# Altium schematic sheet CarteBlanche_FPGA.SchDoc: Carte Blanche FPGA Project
size A1; DrawnBy: SRKH; Engineer: SRKH; DocumentNumber: 1; Revision: CB500E; SheetNumber: 1; SheetTotal: 1
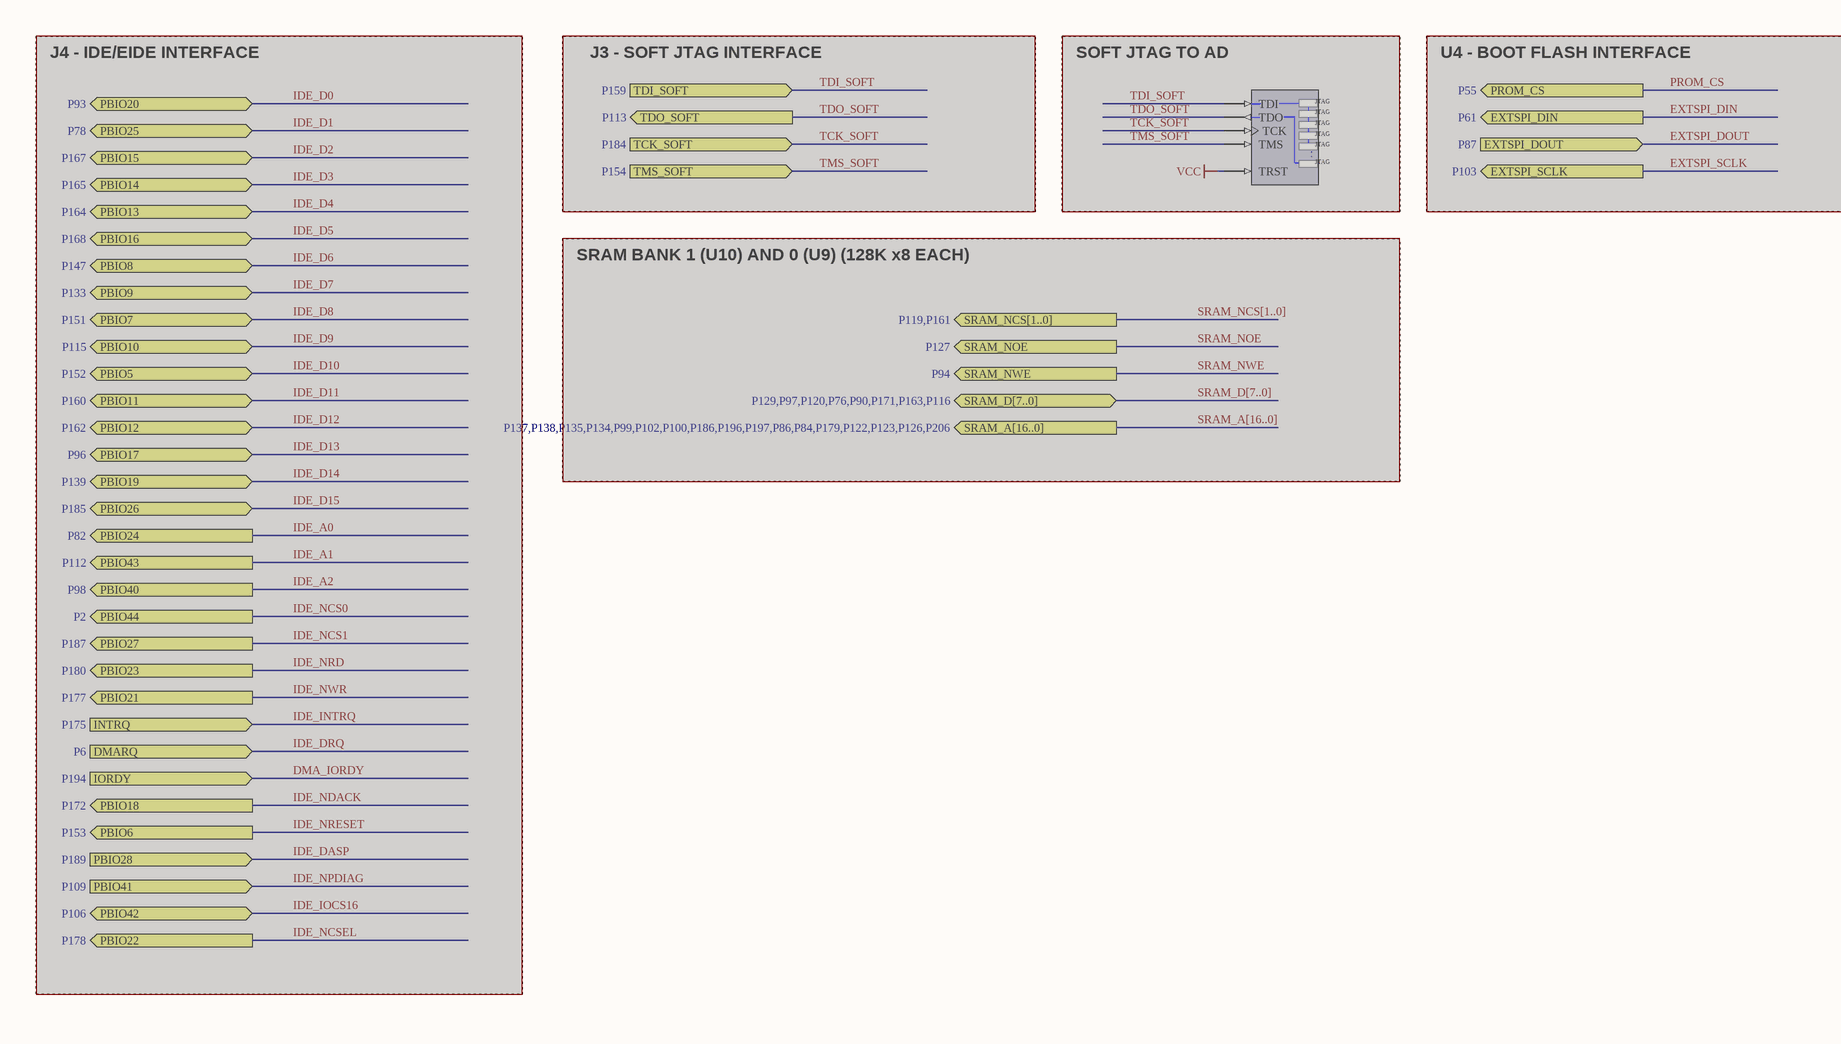
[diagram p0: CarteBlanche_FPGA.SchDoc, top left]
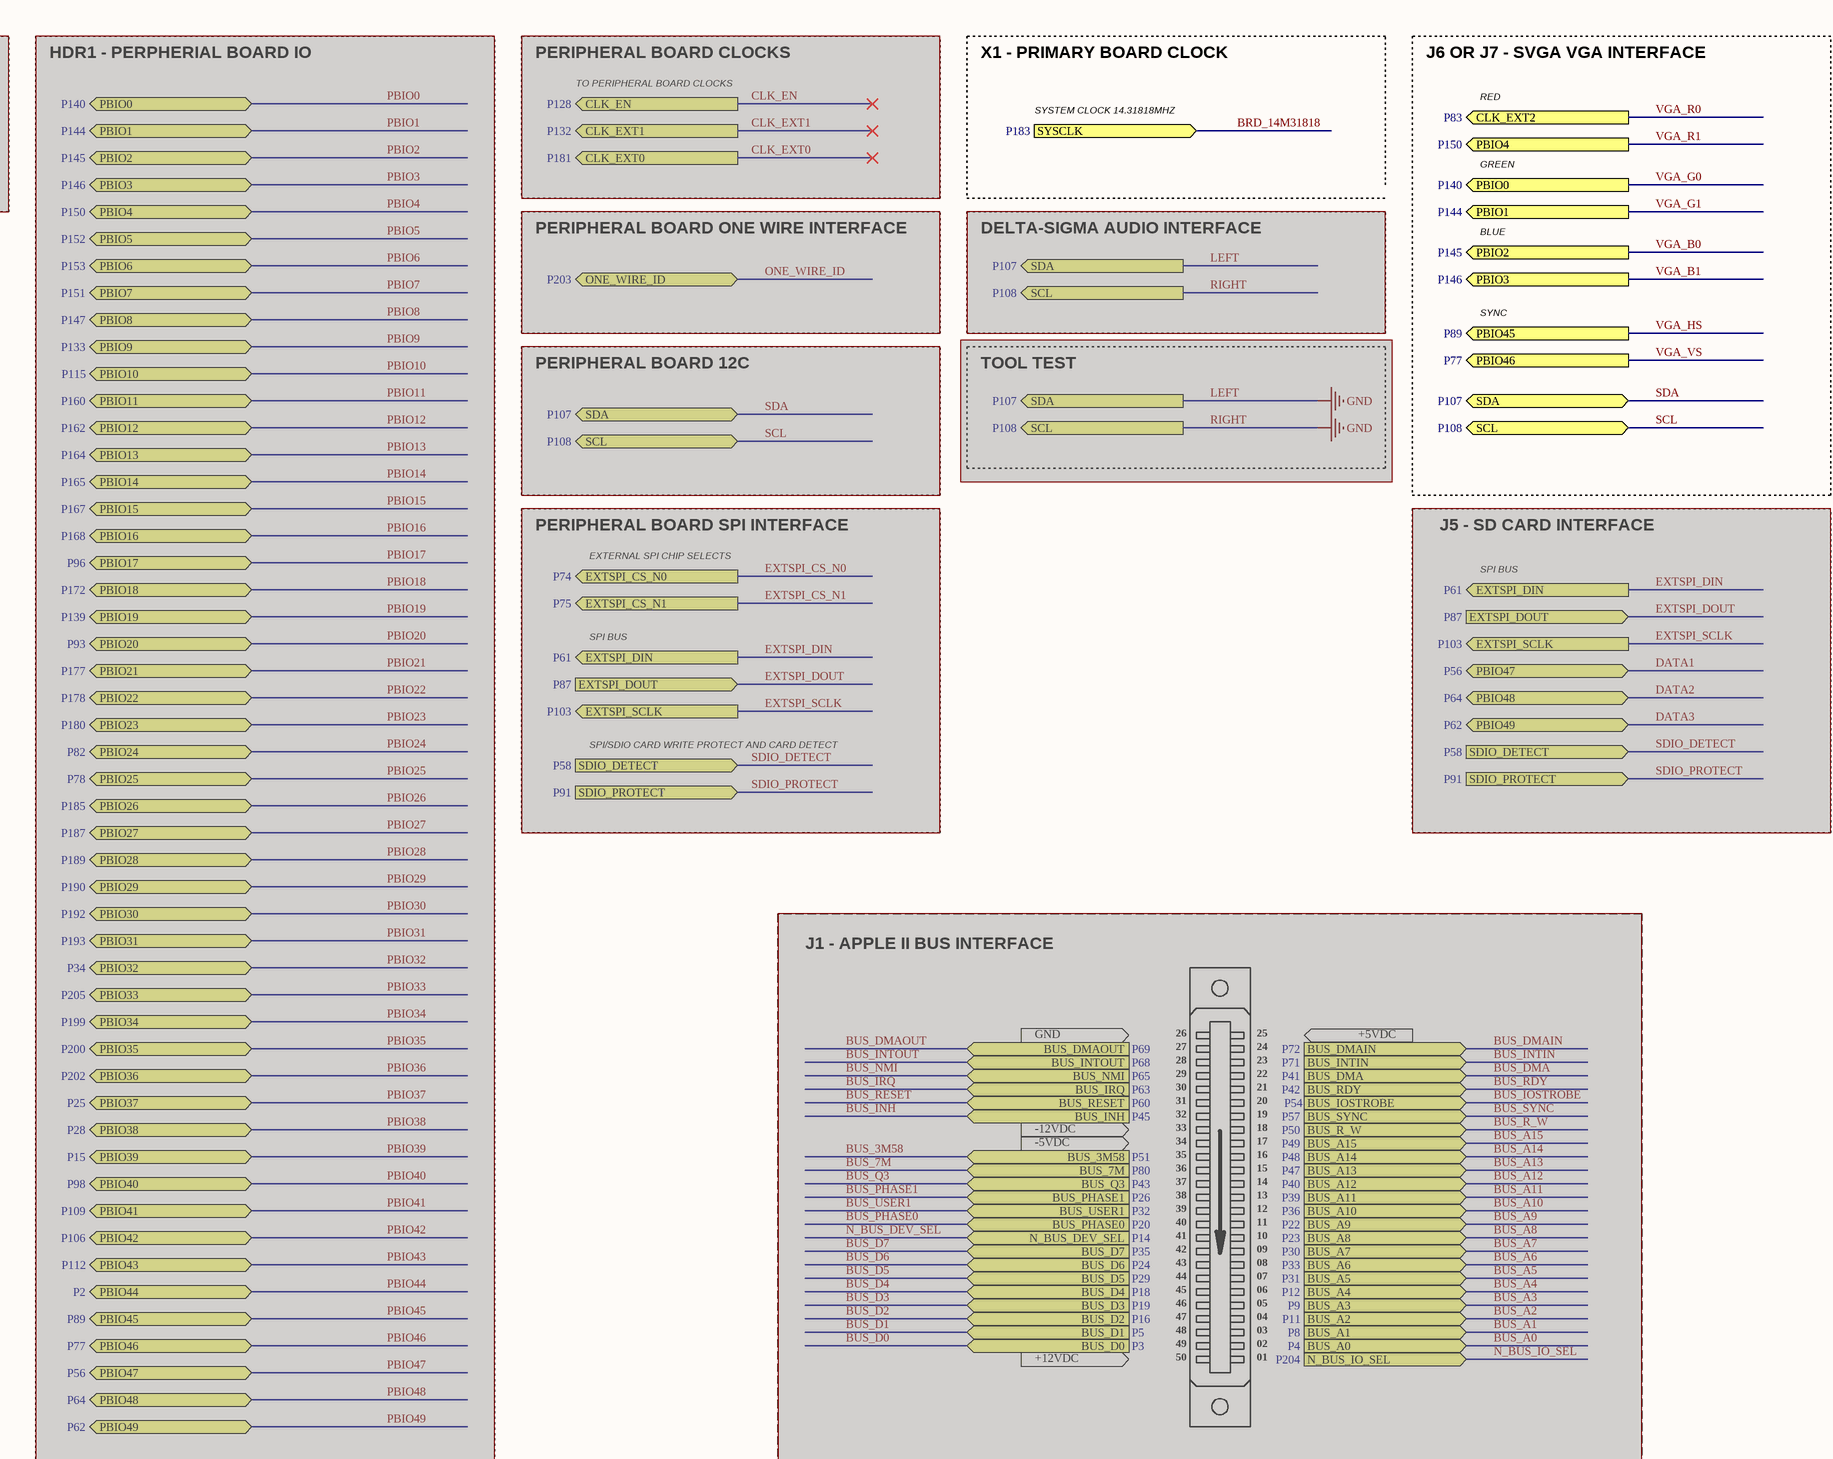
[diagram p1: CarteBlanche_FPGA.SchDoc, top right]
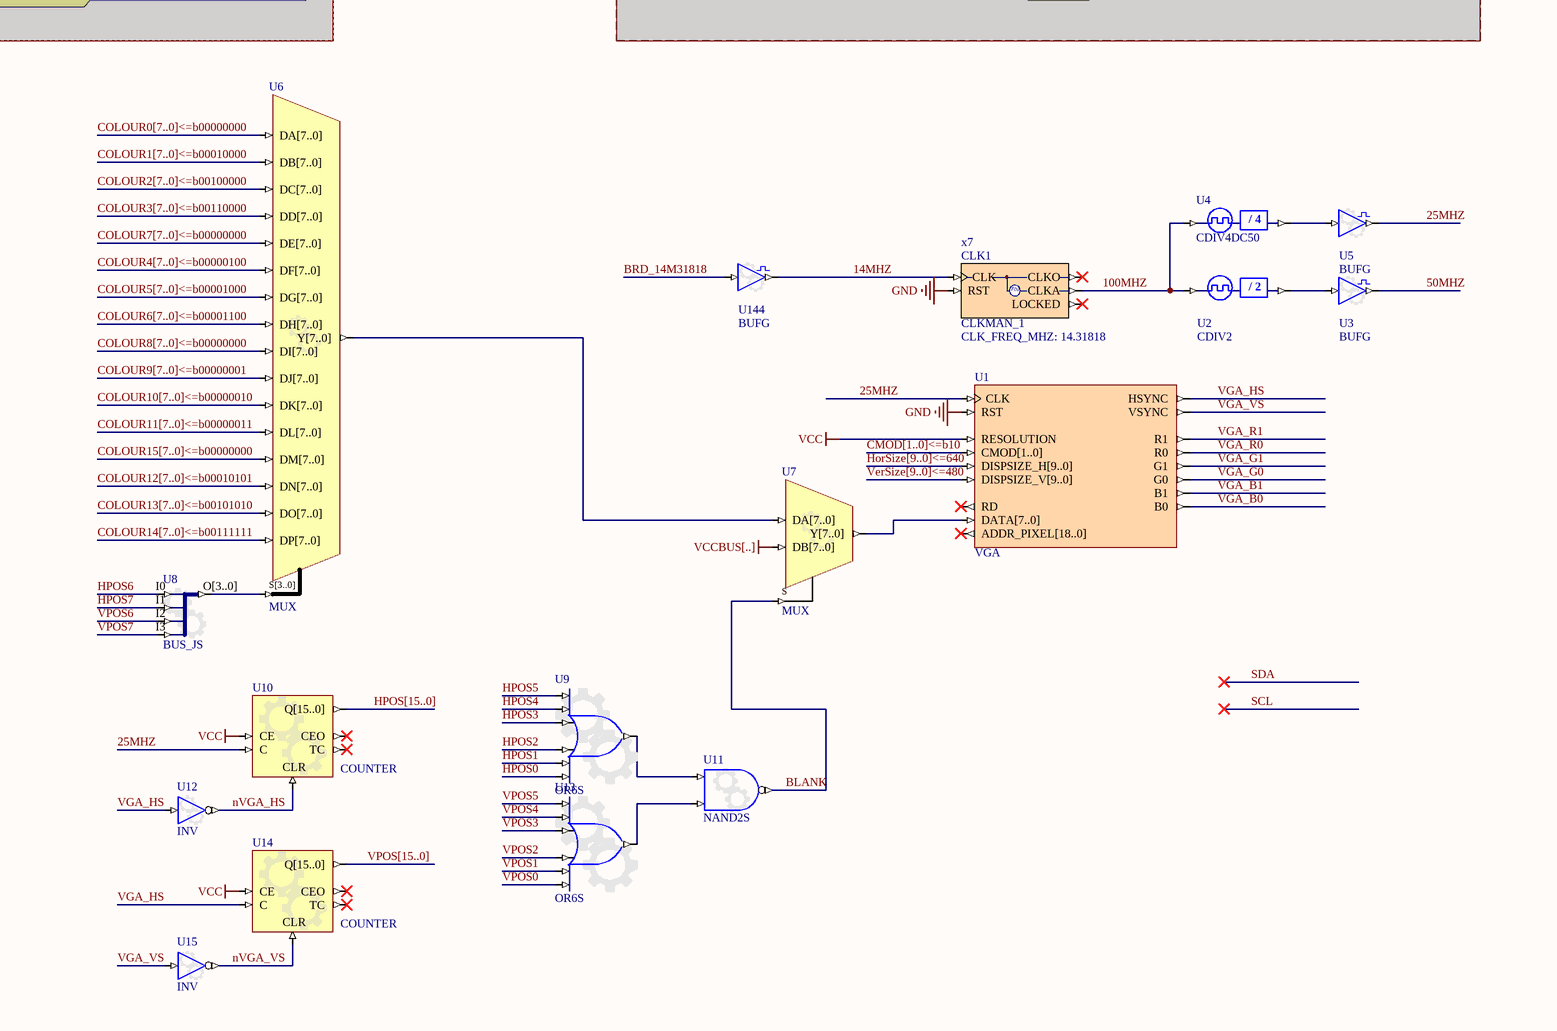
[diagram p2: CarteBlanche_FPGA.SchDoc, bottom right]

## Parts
CLK1  CLKMAN_1  CLK_FREQ_MHZ: 14.31818  ClkA_Operation: x7
NEXUS_JTAG_PORT  NEXUS_JTAG_PORT  (value not drawn)  (masked out: inside a compile mask, not in the netlist)
U1  VGA
U2  CDIV2
U3  BUFG
U4  CDIV4DC50
U5  BUFG
U6  MUX
U7  MUX
U8  BUS_JS
U9  OR6S
U10  COUNTER
U11  NAND2S
U12  INV
U13  OR6S
U14  COUNTER
U15  INV
U144  BUFG

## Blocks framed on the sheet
SOFT JTAG TO AD: NEXUS_JTAG_PORT

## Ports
BUS_3M58 (in, see P51), BUS_7M (in, see P80), BUS_A0 (in, see P4), BUS_A1 (in, see P8), BUS_A2 (in, see P11), BUS_A3 (in, see P9), BUS_A4 (in, see P12), BUS_A5 (in, see P31), BUS_A6 (in, see P33), BUS_A7 (in, see P30), BUS_A8 (in, see P23), BUS_A9 (in, see P22), BUS_A10 (in, see P36), BUS_A11 (in, see P39), BUS_A12 (in, see P40), BUS_A13 (in, see P47), BUS_A14 (in, see P48), BUS_A15 (in, see P49), BUS_D0 (in, see P3), BUS_D1 (in, see P5), BUS_D2 (in, see P16), BUS_D3 (in, see P19), BUS_D4 (in, see P18), BUS_D5 (in, see P29), BUS_D6 (in, see P24), BUS_D7 (in, see P35), BUS_DMA (in, see P41), BUS_DMAIN (in, see P72), BUS_DMAOUT (in, see P69), BUS_INH (in, see P45), BUS_INTIN (in, see P71), BUS_INTOUT (in, see P68), BUS_IOSTROBE (in, see P54), BUS_IRQ (in, see P63), BUS_NMI (in, see P65), BUS_PHASE0 (in, see P20), BUS_PHASE1 (in, see P26), BUS_Q3 (in, see P43), BUS_R_W (in, see P50), BUS_RDY (in, see P42), BUS_RESET (in, see P60), BUS_SYNC (in, see P57), BUS_USER1 (in, see P32), CLK_EN (out, see P128), CLK_EXT0 (out, see P181), CLK_EXT1 (out, see P132), CLK_EXT2 (out, see P83), DMARQ (in, see P6), EXTSPI_CS_N0 (out, see P74), EXTSPI_CS_N1 (out, see P75), EXTSPI_DIN (out, see P61), EXTSPI_DOUT (in, see P87), EXTSPI_SCLK (out, see P103), INTRQ (in, see P175), IORDY (in, see P194), N_BUS_DEV_SEL (in, see P14), N_BUS_IO_SEL (in, see P204), ONE_WIRE_ID (bidir, see P203), PBIO0 (bidir, see P140), PBIO0 (out, see P140), PBIO1 (bidir, see P144), PBIO1 (out, see P144), PBIO2 (bidir, see P145), PBIO2 (out, see P145), PBIO3 (bidir, see P146), PBIO3 (out, see P146), PBIO4 (bidir, see P150), PBIO4 (out, see P150), PBIO5 (bidir, see P152), PBIO6 (bidir, see P153), PBIO6 (out, see P153), PBIO7 (bidir, see P151), PBIO8 (bidir, see P147), PBIO9 (bidir, see P133), PBIO10 (bidir, see P115), PBIO11 (bidir, see P160), PBIO12 (bidir, see P162), PBIO13 (bidir, see P164), PBIO14 (bidir, see P165), PBIO15 (bidir, see P167), PBIO16 (bidir, see P168), PBIO17 (bidir, see P96), PBIO18 (bidir, see P172), PBIO18 (out, see P172), PBIO19 (bidir, see P139), PBIO20 (bidir, see P93), PBIO21 (bidir, see P177), PBIO21 (out, see P177), PBIO22 (bidir, see P178), PBIO22 (out, see P178), PBIO23 (bidir, see P180), PBIO23 (out, see P180), PBIO24 (bidir, see P82), PBIO24 (out, see P82), PBIO25 (bidir, see P78), PBIO26 (bidir, see P185), PBIO27 (bidir, see P187), PBIO27 (out, see P187), PBIO28 (bidir, see P189), PBIO28 (in, see P189), PBIO29 (bidir, see P190), PBIO30 (bidir, see P192), PBIO31 (bidir, see P193), PBIO32 (bidir, see P34), PBIO33 (bidir, see P205), PBIO34 (bidir, see P199), PBIO35 (bidir, see P200), PBIO36 (bidir, see P202), PBIO37 (bidir, see P25), PBIO38 (bidir, see P28), PBIO39 (bidir, see P15), PBIO40 (bidir, see P98), PBIO40 (out, see P98), PBIO41 (bidir, see P109), PBIO41 (in, see P109), PBIO42 (bidir, see P106), PBIO43 (bidir, see P112), PBIO43 (out, see P112), PBIO44 (bidir, see P2), PBIO44 (out, see P2), PBIO45 (bidir, see P89), PBIO45 (out, see P89), PBIO46 (bidir, see P77), PBIO46 (out, see P77), PBIO47 (bidir, see P56), PBIO48 (bidir, see P64), PBIO49 (bidir, see P62), PROM_CS (out, see P55), SCL (bidir, see P108), SCL (out, see P108), SDA (bidir, see P107), SDA (out, see P107), SDIO_DETECT (in, see P58), SDIO_PROTECT (in, see P91), SRAM_A[16..0] (out, see P137,P138,P135,P134,P99,P102,P100,P186,P196,P197,P86,P84,P179,P122,P123,P126,P206), SRAM_D[7..0] (bidir, see P129,P97,P120,P76,P90,P171,P163,P116), SRAM_NCS[1..0] (out, see P119,P161), SRAM_NOE (out, see P127), SRAM_NWE (out, see P94), SYSCLK (in, see P183), TCK_SOFT (in, see P184), TDI_SOFT (in, see P159), TDO_SOFT (out, see P113), TMS_SOFT (in, see P154)

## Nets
GND: CLK1.RST U1.RST
VCC: U1.RESOLUTION U10.CE U14.CE
VCCBUS[..]: U7.DB[7..0]
14MHZ: CLK1.CLK U144.O
25MHZ: U1.CLK U5.O U10.C
50MHZ: U3.O
100MHZ: CLK1.CLKA U2.CLKIN U4.CLKIN
BLANK: U7.S U11.O
BRD_14M31818: U144.I ; port SYSCLK
HPOS0: U9.I5
HPOS1: U9.I4
HPOS2: U9.I3
HPOS3: U9.I2
HPOS4: U9.I1
HPOS5: U9.I0
HPOS6: U8.I0
HPOS7: U8.I1
nVGA_HS: U10.CLR U12.O
nVGA_VS: U14.CLR U15.O
VGA_B0: U1.B0 ; port PBIO2
VGA_B1: U1.B1 ; port PBIO3
VGA_G0: U1.G0 ; port PBIO0
VGA_G1: U1.G1 ; port PBIO1
VGA_HS: U1.HSYNC U12.I U14.C ; port PBIO45
VGA_R0: U1.R0 ; port CLK_EXT2
VGA_R1: U1.R1 ; port PBIO4
VGA_VS: U1.VSYNC U15.I ; port PBIO46
VPOS0: U13.I5
VPOS1: U13.I4
VPOS2: U13.I3
VPOS3: U13.I2
VPOS4: U13.I1
VPOS5: U13.I0
VPOS6: U8.I2
VPOS7: U8.I3
NetU2_CLKDV: U2.CLKDV U3.I
NetU4_CLKDV: U4.CLKDV U5.I
NetU9_O: U9.O U11.I0
NetU11_I1: U11.I1 U13.O

Not connected (* = marked no-connect by the designer): CLK1 CLKO* LOCKED*; U1 ADDR_PIXEL[18..0]* CMOD[1..0] DATA[7..0] DISPSIZE_H[9..0] DISPSIZE_V[9..0] RD*; U6 DA[7..0] DB[7..0] DC[7..0] DD[7..0] DE[7..0] DF[7..0] DG[7..0] DH[7..0] DI[7..0] DJ[7..0] DK[7..0] DL[7..0] DM[7..0] DN[7..0] DO[7..0] DP[7..0] S[3..0] Y[7..0]; U7 DA[7..0] Y[7..0]; U8 O[3..0]; U10 CEO* Q[15..0] TC*; U14 CEO* Q[15..0] TC*

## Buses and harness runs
bus CMOD[1..0]<=b10
bus COLOUR0[7..0]<=b00000000
bus COLOUR1[7..0]<=b00010000
bus COLOUR2[7..0]<=b00100000
bus COLOUR3[7..0]<=b00110000
bus COLOUR4[7..0]<=b00000100
bus COLOUR5[7..0]<=b00001000
bus COLOUR6[7..0]<=b00001100
bus COLOUR7[7..0]<=b00000000
bus COLOUR8[7..0]<=b00000000
bus COLOUR9[7..0]<=b00000001
bus COLOUR10[7..0]<=b00000010
bus COLOUR11[7..0]<=b00000011
bus COLOUR12[7..0]<=b00010101
bus COLOUR13[7..0]<=b00101010
bus COLOUR14[7..0]<=b00111111
bus COLOUR15[7..0]<=b00000000
bus HorSize[9..0]<=640
bus HPOS[15..0]
bus VerSize[9..0]<=480
bus VPOS[15..0]

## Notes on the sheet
- J4 - IDE/EIDE INTERFACE
- J3 - SOFT JTAG INTERFACE
- U4 - BOOT FLASH INTERFACE
- HDR1 - PERPHERIAL BOARD IO
- PERIPHERAL BOARD CLOCKS
- X1 - PRIMARY BOARD CLOCK
- J6 OR J7 - SVGA VGA INTERFACE
- TO PERIPHERAL BOARD CLOCKS
- SYSTEM CLOCK 14.31818MHZ
- RED
- GREEN
- SRAM BANK 1 (U10) AND 0 (U9) (128K x8 EACH)
- PERIPHERAL BOARD ONE WIRE INTERFACE
- DELTA-SIGMA AUDIO INTERFACE
- BLUE
- SYNC
- PERIPHERAL BOARD 12C
- TOOL TEST
- PERIPHERAL BOARD SPI INTERFACE
- J5 - SD CARD INTERFACE
- EXTERNAL SPI CHIP SELECTS
- SPI BUS
- SPI/SDIO CARD WRITE PROTECT AND CARD DETECT
- J1 - APPLE II BUS INTERFACE
- GND
- 26
- 27
- 28
- 29
- 25
- 24
- 23
- 22
- +5VDC
- -12VDC
- 30
- 31
- 32
- 33
- 34
- 21
- 20
- 19
- 18
- 17
- -5VDC
- 35
- 36
- 37
- 38
- 39
- 16
- 15
- 14
- 13
- 12
- 40
- 41
- 42
- 43
- 44
- 11
- 10
- 09
- 08
- 07
- 45
- 46
- 47
- 48
- 49
- 06
- 05
- 04
- 03
- 02
- +12VDC
- 50
- 01

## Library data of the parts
CLK1 = CLKMAN_1: Single Operational Output Clock Manager; Clk_Count: 1
NEXUS_JTAG_PORT = NEXUS_JTAG_PORT: Soft Nexus-Chain Connector; NEXUS_JTAG_CONNECTOR: True
U1 = VGA: VGA Controller
U2 = CDIV2: Clock Divider by 2; DivisorRate: 2; ArchiveName: GENERIC; VHDLIB_SIM: GENERIC_LIB
U3 U5 U144 = BUFG: Configurable Global Clock Buffer; ConfiguratorName: GENERIC_BUFFER; ConfigurationParameters: {}Version[1.1]{}SignalCount[1]{}SignalWidth0[1]{}OutputOption0[Global Clock]{}EnableMode[None]{}ShowPinNames[False]{}
U4 = CDIV4DC50: Clock Divider by 4 with 50% Duty Cycle Output; DivisorRate: 4; ArchiveName: GENERIC; VHDLIB_SIM: GENERIC_LIB; XilinxEquivalent: CLK_DIV4; DutyCycle: 50
U6 = MUX: Configurable Mutliplexer; ConfigurationParameters: {}Version[1.0]{}ShowEnable[False]{}BusInputs[True]{}BusOutputs[True]{}SignalWidth[8]{}Type[Multiplexer]{}RegisterOutputs[False]{}NegativeClockEdge[False]{}ShowPinNames[True]{}InvertSingleSignal[False]{}SignalCount[16]{}Invert0[False]{}Invert1[False]{}Invert2[False]{}Invert3[False]{}Invert4[False]{}Invert5[False]{}Invert6[False]{}Invert7[False]{}Invert8[False]{}Invert9[False]{}Invert10[False]{}Invert11[False]{}Invert12[False]{}Invert13[False]{}Invert14[False]{}Invert15[False]{}; ConfiguratorName: GENERIC_MULTIPLEXER
U7 = MUX: Configurable Mutliplexer; ConfigurationParameters: {}Version[1.0]{}ShowEnable[False]{}BusInputs[True]{}BusOutputs[True]{}SignalWidth[8]{}Type[Multiplexer]{}RegisterOutputs[False]{}NegativeClockEdge[False]{}ShowPinNames[True]{}InvertSingleSignal[False]{}SignalCount[2]{}Invert0[False]{}Invert1[False]{}; ConfiguratorName: GENERIC_MULTIPLEXER
U8 = BUS_JS: Configurable Bus Joiner/Splitter; ConfiguratorName: GENERIC_BUS_JS; ConfigurationParameters: {}Version[1.1]{}SplitterJoinerType[Joiner]{}SignalCount[4]{}SignalWidth0[1]{}GapBelow0[1000000]{}ConnectionType0[Pin]{}SignalWidth1[1]{}GapBelow1[1000000]{}ConnectionType1[Pin]{}SignalWidth2[1]{}GapBelow2[1000000]{}ConnectionType2[Pin]{}SignalWidth3[1]{}GapBelow3[1000000]{}ConnectionType3[Pin]{}ShowPinNames[True]{}
U9 U13 = GATE: Configurable Generic Gate; ConfiguratorName: GENERIC_GATE; ConfigurationParameters: {}Version[1.1]{}GateKind[OR]{}BusInput[False]{}GateInputType[Bit]{}GateOutputOption[Normal]{}BusWidth[8]{}RegisterOutputs[False]{}NegativeClockEdge[False]{}InputCount[6]{}InputInvert0[False]{}InputInvert1[False]{}InputInvert2[False]{}InputInvert3[False]{}InputInvert4[False]{}InputInvert5[False]{}
U10 U14 = COUNTER: Configurable Counter; ConfiguratorName: GENERIC_COUNTER; ConfigurationParameters: {}Version[1.0]{}Type[Binary]{}SyncReset[False]{}NegativeClockEdge[False]{}FixedDirection[True]{}IsIncrement[True]{}SignalWidth[16]{}MaxValue[65535]{}BusOutput[True]{}Loadable[False]{}BusInput[False]{}ShowPinNames[True]{}
U11 = GATE: Configurable Generic Gate; ConfiguratorName: GENERIC_GATE; ConfigurationParameters: {}Version[1.1]{}GateKind[NAND]{}BusInput[False]{}GateInputType[Bit]{}GateOutputOption[Normal]{}BusWidth[8]{}RegisterOutputs[False]{}NegativeClockEdge[False]{}InputCount[2]{}InputInvert0[False]{}InputInvert1[False]{}
U12 U15 = INV: Configurable Inverter; ConfiguratorName: GENERIC_BUFFER; ConfigurationParameters: {}Version[1.1]{}SignalCount[1]{}SignalWidth0[1]{}OutputOption0[Inverted]{}EnableMode[None]{}ShowPinNames[False]{}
